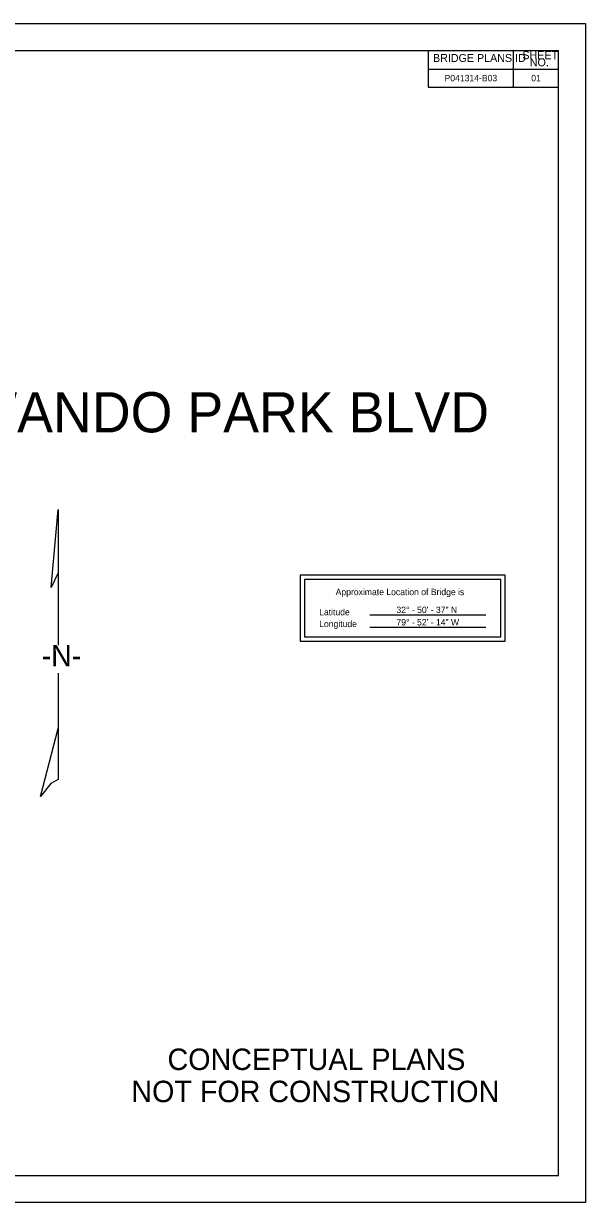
# Model space of a CAD drawing. Extents: x 291 to 2091, y 224 to 1324.
# Drawn here: x 1567 to 2091, y 224 to 1324 of the extents above; entities that cross this region are included whole.
import ezdxf

# ---------------------------------------------------------------- set-up
doc = ezdxf.new("R2010")
doc.units = 0
for name, color, linetype in [('BR_BORDER LINES', 7, 'Continuous'), ('BR_TEXT', 7, 'Continuous'), ('Default', 7, 'Continuous'), ('GN_TitleSheetMap', 7, 'Continuous'), ('RD_SHT_IplotShp', 7, 'Continuous')]:
    doc.layers.add(name, color=color, linetype=linetype)

msp = doc.modelspace()

# ---------------------------------------------------------------- linework, layer by layer
at = {"layer": 'BR_BORDER LINES'}
for p, q in [((391.1, 1299), (2066.1, 1299)), ((1944.4, 1299), (1944.4, 1264.8)), ((2023.9, 1264.8), (2023.9, 1299)), ((2066.1, 249.1), (2066.1, 1299)), ((1944.4, 1281.5), (2066.1, 1281.5)), ((2066.1, 1240.8), (2066.1, 1265.7)), ((1944.4, 1264.8), (2066.1, 1264.8)), ((2066.1, 888.4), (2066.1, 1240.8)), ((391.1, 249.1), (2066.1, 249.1))]:
    msp.add_line(p, q, dxfattribs=at)
at = {"layer": 'BR_TEXT'}
for points in [[(2016.1, 809.3), (1825, 809.3), (1825, 747.7), (2016.1, 747.7)], [(2012.1, 805.3), (1829, 805.3), (1829, 751.7), (2012.1, 751.7)]]:
    msp.add_lwpolyline(points, close=True, dxfattribs=at)
at = {"layer": 'Default'}
for p, q in [((1592.6, 797.9), (1599.3, 870.7)), ((1599.3, 870.7), (1599.3, 811.4)), ((1599.3, 811.4), (1592.6, 797.9)), ((1599.3, 811.4), (1599.3, 770.3)), ((1599.3, 770.3), (1599.3, 744.1)), ((1599.3, 718), (1599.3, 666.2)), ((1582.8, 602.7), (1599.3, 666.2)), ((1599.3, 666.2), (1599.3, 658.3)), ((1599.3, 658.3), (1599.3, 618.6))]:
    msp.add_line(p, q, dxfattribs=at)
msp.add_lwpolyline([(1599.3, 618.6), (1592.2, 614.8), (1582.8, 602.7)], dxfattribs=at)
at = {"layer": 'GN_TitleSheetMap'}
for p, q in [((1890, 772.3), (1998.1, 772.3)), ((1890, 760.7), (1998.1, 760.7))]:
    msp.add_line(p, q, dxfattribs=at)
at = {"layer": 'RD_SHT_IplotShp'}
msp.add_lwpolyline([(291.1, 1324), (2091.1, 1324), (2091.1, 224), (291.1, 224)], close=True, dxfattribs=at)

# ---------------------------------------------------------------- texts
at = {"layer": 'BR_TEXT'}
for s, height, p in [('SHEET', 7.47, (2032.3, 1290.8)), ('BRIDGE PLANS ID', 7.466, (1948.9, 1288.2)), ('NO.', 7.47, (2039.2, 1284.2)), ('CONSTRUCT BRIDGE OVER I-526 & WANDO PARK BLVD', 37.5, (647, 942.6)), ('Approximate Location of Bridge is', 6, (1858.1, 790.7)), ('Latitude', 6, (1842.7, 771.9)), ('32%%D - 50\' - 37" N', 6, (1914.8, 774)), ('Longitude', 6, (1842.7, 760.9)), ('79%%D - 52\' - 14" W', 6, (1914.8, 762.4)), ('CONCEPTUAL PLANS', 20, (1701.2, 347.6)), ('NOT FOR CONSTRUCTION', 20, (1667.5, 317.6))]:
    msp.add_text(s, height=height, dxfattribs=at).set_placement(p)
for s, height, p in [('P041314-B03', 5.999, (1959.7, 1270.2)), ('01', 6, (2040.6, 1270.2))]:
    msp.add_text(s, height=height, rotation=0.0002, dxfattribs=at).set_placement(p)
at = {"layer": 'Default'}
msp.add_text('-N-', height=20, dxfattribs=at).set_placement((1583.7, 724.3))

doc.saveas('drawing.dxf')
